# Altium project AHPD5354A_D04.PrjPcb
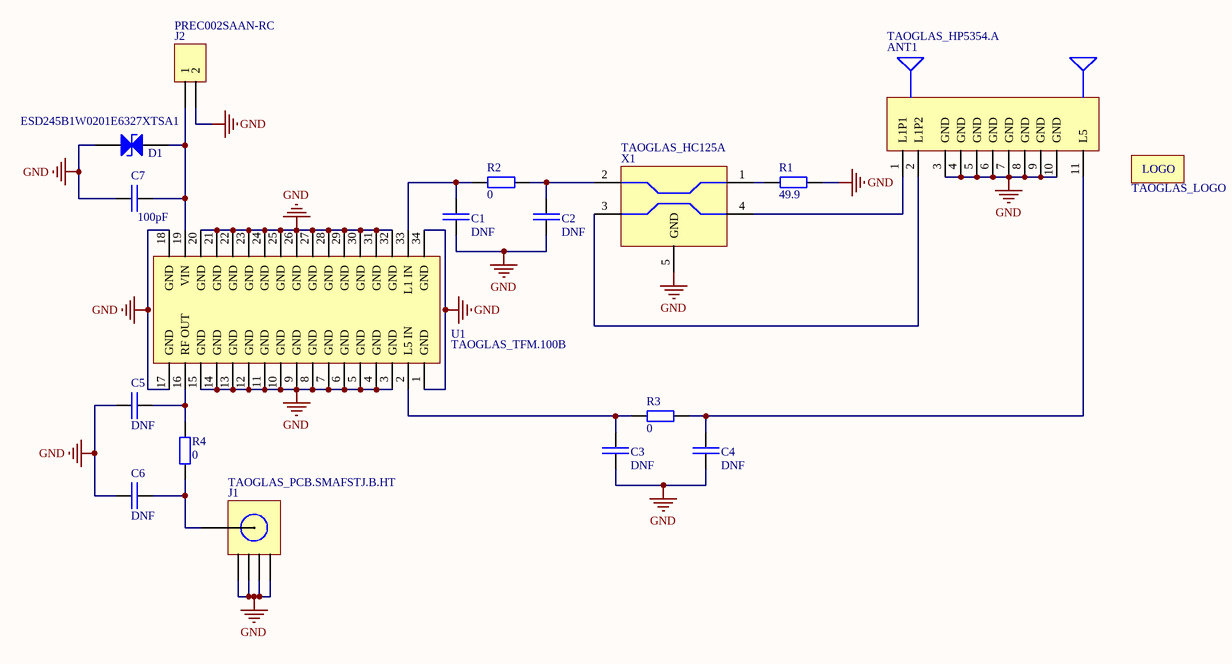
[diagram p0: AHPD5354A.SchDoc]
1 sheet, 18 parts. Net scope: global (net labels, ports and power ports of the same name join across sheets).
Board file: AHPD5354A_D04.PcbDoc

## Sheet AHPD5354A.SchDoc
size Tabloid; SheetNumber: 1; SheetTotal: 1; ProjName: AHPD5354A_D04.PrjPcb

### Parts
ANT1  TAOGLAS_HP5354.A  [TAOGLAS_HP5354.A]
C1  DNF  [0402 - DNF]
C2  DNF  [0402 - DNF]
C3  DNF  [0402 - DNF]
C4  DNF  [0402 - DNF]
C5  DNF  [0402 - DNF]
C6  DNF  [0402 - DNF]
C7  value 100pF  [Capacitor - 0402 - GRM]  (hidden comment: Capacitor_Ceramic_1005(0402)_L1_W0.5_H0.5mm_100pF+-5%_50V_-55 to 125C_Murata_GRM1555C1H101JA01)
D1  ESD245B1W0201E6327XTSA1  [Diode - 0201 (0603 Metric) - DSN0603-2]
J1  TAOGLAS_PCB.SMAFSTJ.B.HT  [TAOGLAS_PCB.SMAFSTJ.B.HT]
J2  PREC002SAAN-RC  [SULLINS_PREC002SAAN-RC]
LOGO  TAOGLAS_LOGO  [TAOGLAS_LOGO - No R - 10.3mm]  (no BOM)
R1  value 49.9  [Resistor - 0402 - RC_L]  (hidden comment: Resistor_Thick Film_1005(0402)_49.9Ohms+-1%_0.063W)
R2  value 0  [Resistor - 0402 - RC_L]  (hidden comment: Resistor_Thick Film_1005(0402)_0Ohm)
R3  value 0  [Resistor - 0402 - RC_L]  (hidden comment: Resistor_Thick Film_1005(0402)_0Ohm)
R4  value 0  [Resistor - 0402 - RC_L]  (hidden comment: Resistor_Thick Film_1005(0402)_0Ohm)
U1  TAOGLAS_TFM.100B  [TAOGLAS_TFM.100B]
X1  TAOGLAS_HC125A  [TAOGLAS_HC125A]

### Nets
GND: ANT1.3(GND) ANT1.4(GND) ANT1.5(GND) ANT1.6(GND) ANT1.7(GND) ANT1.8(GND) ANT1.9(GND) ANT1.10(GND) C1.1 C2.2 C3.1 C4.1 C5.1 C6.1 C7.1 D1.2(ANODE) J1.2(GND) J1.3(GND) J1.4(GND) J1.5(GND) J2.2 R1.1 U1.1(GND) U1.3(GND) U1.4(GND) U1.5(GND) U1.6(GND) U1.7(GND) U1.8(GND) U1.9(GND) U1.10(GND) U1.11(GND) U1.12(GND) U1.13(GND) U1.14(GND) U1.15(GND) U1.17(GND) U1.18(GND) U1.20(GND) U1.21(GND) U1.22(GND) U1.23(GND) U1.24(GND) U1.25(GND) U1.26(GND) U1.27(GND) U1.28(GND) U1.29(GND) U1.30(GND) U1.31(GND) U1.32(GND) U1.34(GND) X1.5(GND)
NetANT1_1: ANT1.1(L1P1) X1.4
NetANT1_2: ANT1.2(L1P2) X1.3
NetANT1_11: ANT1.11(L5) C4.2 R3.2
NetC1_2: C1.2 R2.1 U1.33(L1_IN)
NetC2_1: C2.1 R2.2 X1.2
NetC3_2: C3.2 R3.1 U1.2(L5_IN)
NetC5_2: C5.2 R4.2 U1.16(RF_OUT)
NetC6_2: C6.2 J1.1 R4.1
NetC7_2: C7.2 D1.1(CATHODE) J2.1 U1.19(VIN)
NetR1_2: R1.2 X1.1

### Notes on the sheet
- Labels drawn without touching a wire or pin: GND

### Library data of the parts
ANT1 = CMP-364-000001-9: Low Profile Multi-Band GNSS L1/L5 Patch Antenna; ComponentLibStatus: Created; Temp_Low: -40C; Temp_High: +85C
C1-C6 = CMP-00006-21: Do Not Fit
C7 = CMP-001-00343-45: 100 pF ±5% 50V Ceramic Capacitor C0G, NP0 0402 (1005 Metric); MFG: Murata Electronics; MFGPN: GRM1555C1H101JA01D; Product Status: Not For New Designs
D1 = CMP-004-00167-10: 7.5V Clamp 5.5A (8/20µs) Ipp Tvs Diode Surface Mount WLL-2-3; Voltage - Reverse Standoff (Typ): 5.5V; MFG: Infineon Technologies; Type: Zener; Capacitance @ Frequency: 5.8pF @ 1GHz; Power Line Protection: No; Base Product Number: ESD245; Bidirectional Channels: 1; Power - Peak Pulse: 44W
J1 = CMP-028-000009-10: SMA (F) Surface Mount PCB Jack; ComponentLibStatus: Created; Temp_High: +85C; Temp_Low: -40C
J2 = CMP-002-00180-7: Connector Header Through Hole 2 position 0.100" (2.54mm); MFG: Sullins Connector Solutions; Connector Type: BOARD CONNECTOR; Number of Positions: 2; Temp_Low: -40°C; Angle: 180°; Product Status: Active; Temp_High: 105°C
LOGO = CMP-048-000000-2: Silkscreen Logo - Standard
R1 = CMP-009-00330-4: 49.9 Ohms ±1% 0.1W, 1/10W Chip Resistor 0402 (1005 Metric) Automotive AEC-Q200 Thick Film; Temperature Coefficient: ±100ppm/°C; Product Status: Active; MFG: YAGEO; MFGPN: RC0402FR-0749R9L; Power (Watts): 63mW
R2-R4 = CMP-009-00375-4: 0 Ohms Jumper Chip Resistor 0402 (1005 Metric) Moisture Resistant Thick Film; Product Status: Active; MFGPN: RC0402JR-070RL; MFG: YAGEO
U1 = CMP-266-000001-10: Surface mount GNSS front-end module covering L1/L5; Temp_High: +85C; ComponentLibStatus: Created; Temp_Low: -40C
X1 = CMP-002-000151-19: Low Profile, High Performance Multiband GNSS Hybrid Coupler; Center Frequency: 1.39GHz; Product Status: Active; MFGPN: HC125A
